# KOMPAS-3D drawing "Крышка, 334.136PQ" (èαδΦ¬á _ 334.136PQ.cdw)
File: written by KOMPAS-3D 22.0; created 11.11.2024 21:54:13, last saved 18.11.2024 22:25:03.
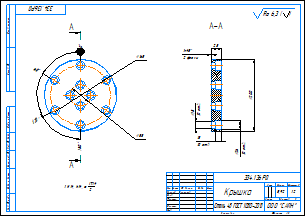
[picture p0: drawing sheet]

Sheet 1: A3, landscape

Document properties: Автор: aleksander.larionov.10@gmail.com; Знак неуказанной шероховатости: 4; Параметр неуказанной шероховатости: Ra 6,3; Полное имя файла: Крышка _ 334.136PQ.m3d; Масса: 5.920024

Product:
- Part/product: Крышка  | designation 334.136PQ
    Материал: Сталь 45 ГОСТ 1050-2013 (density 7810 kg/m3)
    Масса: 5.920024

Title block, sheet 1: Наименование: Крышка; designation: 334.136PQ; Материал: Сталь 45 ГОСТ 1050-2013; Масса: 5,92; Количество листов документа: 1; organisation: ООО "САЙН"; Форматы листов документа: A3; stored path: C:\Мои папки\Работа\Крышки, фланцы\334.136PQ\Крышка _ 334.136PQ.cdw; Разработал: Ларионов

Views: Вид 1, Сверху, Разрез А-А
Referenced files in C:\Мои папки\Работа\Крышки, фланцы\334.136PQ\: Крышка _ 334.136PQ.m3d
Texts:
  Ra 6,3
  Ra 6,3 ( )
Dimensions and other numbers on the sheet: 120; 180; 165; 58; 1 H14, h14,    IT14 2 .; 334.136PQ; 200; 26; 10 отв.; 18; 28; 1; 2 фаски; 1:2; 5,92; 334.136PQ Крышка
